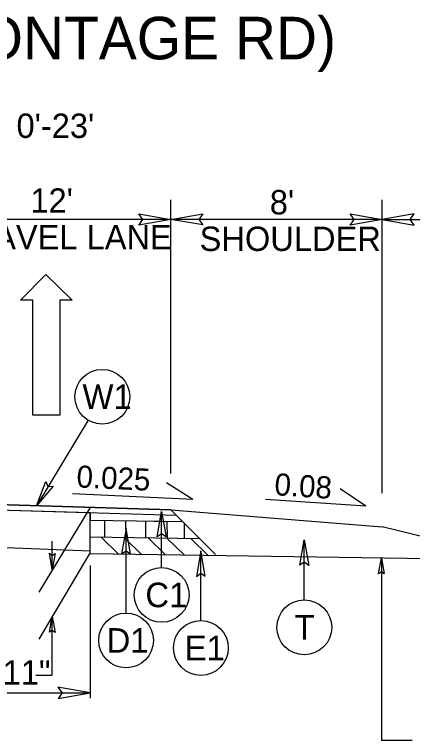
# Model space of a CAD drawing. Extents: x 2176156 to 2177167, y 76401 to 76644.
# Drawn here: x 2176834.8 to 2176853.62, y 76511.15 to 76545.49 of the extents above; entities that cross this region are included whole.
import ezdxf

# ---------------------------------------------------------------- set-up
doc = ezdxf.new("R2010")
doc.units = 0
for name, color, linetype in [('Exist Building', 7, 'Continuous'), ('Exist Roads Curbs', 7, 'Continuous'), ('Exist Roads EOP Other', 7, 'Continuous'), ('Exist Roads Soil', 7, 'Continuous'), ('Exist Structure Minor Culvert Topo', 7, 'Continuous'), ('Exist Structure Minor Drop Inlet', 7, 'Continuous'), ('Exist Utilities Other Pole CELL', 7, 'Continuous'), ('Exist Vegetation Woods Line', 7, 'Continuous'), ('Model Boundary Lines Text', 7, 'Continuous'), ('Old_Level_1', 7, 'Continuous'), ('Old_Level_3', 7, 'Continuous'), ('Prop North Arrow NAD83 for Plan Sheets CELL', 7, 'Continuous'), ('Sheet Plan CELL', 7, 'Continuous')]:
    doc.layers.add(name, color=color, linetype=linetype)

msp = doc.modelspace()

# ---------------------------------------------------------------- linework, layer by layer
at = {"layer": 'Exist Building'}
for p, q in [((2176838.376, 76519.975), (2176838.376, 76521.926)), ((2176858.521, 76519.675), (2176838.376, 76519.975))]:
    msp.add_line(p, q, dxfattribs=at)
at = {"layer": 'Exist Roads Curbs'}
for p, q in [((2176822.186, 76522.431), (2176842.453, 76521.799)), ((2176830.194, 76522.432), (2176842.194, 76522.057)), ((2176842.194, 76522.057), (2176830.194, 76522.432)), ((2176830.194, 76522.182), (2176838.376, 76521.926)), ((2176842.453, 76521.799), (2176842.194, 76522.057))]:
    msp.add_line(p, q, dxfattribs=at)
msp.add_lwpolyline([(2176838.376, 76521.926), (2176838.376, 76521.568), (2176840.564, 76521.536), (2176841.396, 76521.523), (2176842.751, 76521.503), (2176842.453, 76521.799)], dxfattribs=at)
at = {"layer": 'Exist Roads EOP Other'}
for p in [(2176842.194, 76522.057), (2176860.146, 76519.269)]:
    msp.add_line(p, (2176852.194, 76521.257), dxfattribs=at)
at = {"layer": 'Exist Roads Soil'}
for p, q in [((2176842.194, 76522.057), (2176844.31, 76519.953)), ((2176838.376, 76521.568), (2176842.751, 76521.503)), ((2176838.376, 76520.782), (2176843.554, 76520.704))]:
    msp.add_line(p, q, dxfattribs=at)
at = {"layer": 'Exist Structure Minor Drop Inlet'}
for p, q in [((2176835.08, 76531.971), (2176836.282, 76533.193)), ((2176836.282, 76533.193), (2176837.524, 76531.971)), ((2176835.662, 76531.971), (2176835.08, 76531.971)), ((2176835.662, 76526.539), (2176835.662, 76531.971)), ((2176837.524, 76531.971), (2176836.942, 76531.971)), ((2176836.942, 76531.971), (2176836.942, 76526.539)), ((2176836.942, 76526.539), (2176835.662, 76526.539))]:
    msp.add_line(p, q, dxfattribs=at)
at = {"layer": 'Exist Utilities Other Pole CELL'}
for p, q in [((2176843.231, 76522.543), (2176841.99, 76523.339)), ((2176851.422, 76522.233), (2176850.197, 76523.053)), ((2176843.231, 76522.543), (2176837.551, 76522.808)), ((2176851.422, 76522.233), (2176846.676, 76522.547))]:
    msp.add_line(p, q, dxfattribs=at)
at = {"layer": 'Model Boundary Lines Text'}
for p, q in [((2176839.08, 76520.771), (2176839.069, 76521.558)), ((2176840.077, 76520.756), (2176840.066, 76521.543)), ((2176841.018, 76520.742), (2176841.006, 76521.529)), ((2176842.036, 76520.727), (2176842.024, 76521.514)), ((2176842.849, 76520.715), (2176842.839, 76521.416)), ((2176839.733, 76519.945), (2176838.898, 76520.764)), ((2176840.823, 76519.937), (2176839.988, 76520.755)), ((2176841.942, 76519.933), (2176841.107, 76520.751)), ((2176842.836, 76519.914), (2176842.009, 76520.724)), ((2176843.976, 76519.882), (2176843.141, 76520.7))]:
    msp.add_line(p, q, dxfattribs=at)
at = {"layer": 'Old_Level_1'}
for points in [[(2176843.703, 76535.535), (2176842.194, 76535.795), (2176843.712, 76536.063), (2176843.519, 76535.795)], [(2176840.684, 76536.055), (2176842.194, 76535.795), (2176840.676, 76535.527), (2176840.869, 76535.795)], [(2176850.684, 76536.055), (2176852.194, 76535.795), (2176850.676, 76535.527), (2176850.869, 76535.795)], [(2176853.703, 76536.055), (2176852.194, 76535.795), (2176853.712, 76535.527), (2176853.519, 76535.795)], [(2176836.72, 76519.998), (2176836.588, 76519.244), (2176836.456, 76520.003), (2176836.59, 76519.906)], [(2176852.025, 76519.03), (2176852.155, 76519.785), (2176852.289, 76519.026), (2176852.155, 76519.122)], [(2176836.455, 76516.265), (2176836.588, 76517.019), (2176836.72, 76516.26), (2176836.586, 76516.357)], [(2176836.866, 76513.143), (2176838.376, 76513.403), (2176836.858, 76513.671), (2176837.051, 76513.403)]]:
    msp.add_lwpolyline(points, close=True, dxfattribs=at)
at = {"layer": 'Old_Level_3'}
for p, q in [((2176842.194, 76523.783), (2176842.194, 76536.723)), ((2176852.194, 76522.855), (2176852.194, 76536.723)), ((2176842.194, 76535.795), (2176830.194, 76535.795)), ((2176852.194, 76535.795), (2176842.194, 76535.795)), ((2176852.194, 76535.795), (2176860.181, 76535.795)), ((2176838.376, 76522.176), (2176835.951, 76518.168)), ((2176836.588, 76519.244), (2176836.588, 76520.572)), ((2176838.376, 76520.038), (2176835.951, 76515.944)), ((2176852.155, 76519.785), (2176852.155, 76511.15)), ((2176838.376, 76519.43), (2176838.376, 76513.149)), ((2176836.588, 76514.243), (2176836.588, 76517.019)), ((2176835.808, 76514.243), (2176836.588, 76514.243)), ((2176812.066, 76513.403), (2176838.376, 76513.403)), ((2176853.609, 76511.15), (2176852.155, 76511.15))]:
    msp.add_line(p, q, dxfattribs=at)
at = {"layer": 'Prop North Arrow NAD83 for Plan Sheets CELL'}
for p, q in [((2176838.284, 76526.299), (2176835.839, 76522.255)), ((2176841.76, 76519.33), (2176841.76, 76521.98)), ((2176840.079, 76517.178), (2176840.079, 76521.178)), ((2176848.507, 76517.796), (2176848.507, 76520.638)), ((2176843.616, 76516.822), (2176843.616, 76520.118))]:
    msp.add_line(p, q, dxfattribs=at)
for points in [[(2176836.637, 76523.175), (2176835.839, 76522.255), (2176836.281, 76523.398), (2176836.384, 76523.157)], [(2176841.553, 76520.78), (2176841.76, 76521.98), (2176841.973, 76520.774), (2176841.76, 76520.927)], [(2176840.286, 76519.978), (2176840.079, 76521.178), (2176839.866, 76519.972), (2176840.079, 76520.125)], [(2176848.301, 76519.438), (2176848.507, 76520.638), (2176848.721, 76519.432), (2176848.507, 76519.585)], [(2176843.823, 76518.918), (2176843.616, 76520.118), (2176843.403, 76518.912), (2176843.616, 76519.065)]]:
    msp.add_lwpolyline(points, close=True, dxfattribs=at)
for centre in [(2176838.955, 76527.408), (2176841.76, 76518.034), (2176848.507, 76516.5), (2176840.079, 76515.882), (2176843.616, 76515.526)]:
    msp.add_circle(centre, 1.296, dxfattribs=at)
at = {"layer": 'Sheet Plan CELL'}
msp.add_line((2176838.376, 76520.111), (2176821.519, 76520.722), dxfattribs=at)

# ---------------------------------------------------------------- texts
at = {"layer": 'Exist Structure Minor Culvert Topo'}
for s, height, p in [("VARIES 0'-23'", 1.15334, (2176828.812, 76539.649)), ("12'", 1.1533, (2176835.554, 76536.111)), ("8' ", 1.1533, (2176846.876, 76536.033)), ('TRAVEL LANE', 1.15334, (2176831.785, 76534.381)), ('SHOULDER', 1.1533, (2176843.557, 76534.303))]:
    msp.add_text(s, height=height, dxfattribs=at).set_placement(p)
at = {"layer": 'Exist Utilities Other Pole CELL'}
for s, rotation, p in [('0.025', 357.3324, (2176837.717, 76523.122)), ('0.08', 356.2199, (2176847.072, 76522.757))]:
    msp.add_text(s, height=1.0429, rotation=rotation, dxfattribs=at).set_placement(p)
at = {"layer": 'Exist Vegetation Woods Line'}
msp.add_text('C -Y4- (FRONTAGE RD)', height=2.01314, dxfattribs=at).set_placement((2176820.098, 76543.366))
at = {"layer": 'Prop North Arrow NAD83 for Plan Sheets CELL'}
for s, rotation, p in [('W1', 0.0003, (2176838.018, 76526.828)), ('C1', 0.0003, (2176840.991, 76517.454)), ('T', 359.9997, (2176848.05, 76515.92)), ('D1', 359.9997, (2176839.158, 76515.302)), ('E1', 359.9997, (2176842.853, 76514.946))]:
    msp.add_text(s, height=1.16, rotation=rotation, dxfattribs=at).set_placement(p)
msp.add_text('11"', height=1.1533, dxfattribs=at).set_placement((2176834.242, 76513.794))

doc.saveas('drawing.dxf')
